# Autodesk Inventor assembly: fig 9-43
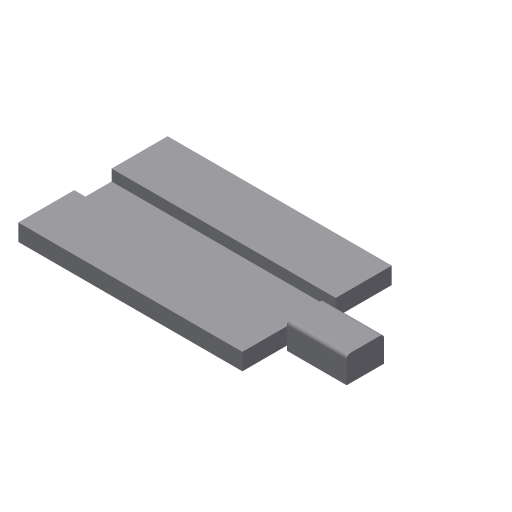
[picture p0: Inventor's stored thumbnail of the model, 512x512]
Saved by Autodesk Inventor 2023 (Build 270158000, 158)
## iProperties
Created: 2013-07
Part Number: fig 9-43
Document SubType Name: Assembly
Designer: CADCIM
Author: CADCIM
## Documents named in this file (3)
- D:\PROJECTS\Project 2022\Autodesk Inventor For Professional 2023\RESOURCES INVENTOR 2023\RESOURCES INVENTOR 2023\Inventor_2023_Part\Inventor_2023_Part\c09_Inv_2023_prt\fig 9-44.iam
- D:\PROJECTS\Project 2022\Autodesk Inventor For Professional 2023\RESOURCES INVENTOR 2023\RESOURCES INVENTOR 2023\Inventor_2023_Part\Inventor_2023_Part\c09_Inv_2023_prt\15.ipt
- D:\PROJECTS\Project 2022\Autodesk Inventor For Professional 2023\RESOURCES INVENTOR 2023\RESOURCES INVENTOR 2023\Inventor_2023_Part\Inventor_2023_Part\c09_Inv_2023_prt\16.ipt
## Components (2 placed, 2 different names)
1. 15:1
2. 16:1
